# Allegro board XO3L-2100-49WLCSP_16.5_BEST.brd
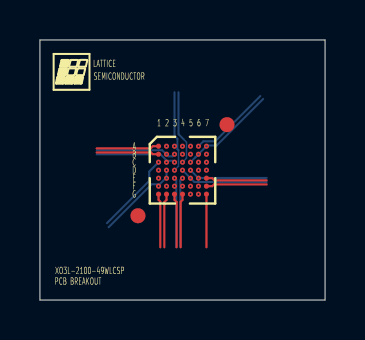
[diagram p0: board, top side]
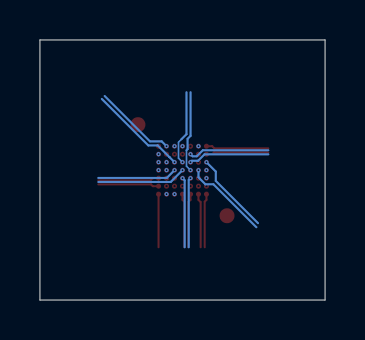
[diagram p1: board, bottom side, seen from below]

Outline 14.28 x 13.02 mm; copper layers: TOP, L2_SIG, L3_PWR_GND, BOTTOM. Coordinates in mm from the lower left corner of the outline.
Outline path: 0,13.02 0,0 14.28,0 14.28,13.02 0,13.02

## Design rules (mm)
net group CDPT20: nets PT20C PT20D
net group CDPT24: nets PT24C PT24D
net group LVDSI_14_PB12: nets LVDSI_14_PB12A LVDSI_14_PB12B
net group LVDSI_23_PB3: nets LVDSI_23_PB3A LVDSI_23_PB3B
net group LVDSI_PB11: nets LVDSI_PB11A LVDSI_PB11B
net group LVDSI_PB16: nets LVDSI_PB16A LVDSI_PB16B
net group LVDSI_PB25: nets LVDSI_PB25A LVDSI_PB25B
net group LVDSO_4_PT17: nets LVDSO_4_PT17A LVDSO_4_PT17B
net group PB8: nets PB8A PB8B
net group PL2: nets PL2A PL2B
net group PL3: nets PL3A PL3B
net group PL5: nets PL5A PL5B
net group PT10: nets PT10A PT10B
net group PT12: nets PT12C PT12D
net group PT16: nets PT16C PT16D
net group PT18: nets PT18C PT18D
net group PT20: nets PT20A PT20B
net group PT23: nets PT23A PT23B
net group PT24: nets PT24A PT24B

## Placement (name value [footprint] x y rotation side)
BGA  -  [BGA49N40P7X7_317X310X60B26N]  7.14 6.5 270 top
NOREF  -  []  0.41 10.21 0 top

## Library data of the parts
BGA = BGA49N40P7X7_317X310X60B26N

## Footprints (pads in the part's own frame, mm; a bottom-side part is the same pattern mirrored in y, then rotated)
BGA49N40P7X7_317X310X60B26N
  round 0.75 smd: (-2.28,2.23) (2.28,-2.23)
  round 0.254 smd: A1(-1.2,-1.2) A2(-1.2,-0.8) A3(-1.2,-0.4) A4(-1.2,0) A5(-1.2,0.4) A6(-1.2,0.8) A7(-1.2,1.2) B1(-0.8,-1.2) B2(-0.8,-0.8) B3(-0.8,-0.4) B4(-0.8,0) B5(-0.8,0.4) B6(-0.8,0.8) B7(-0.8,1.2) C1(-0.4,-1.2) C2(-0.4,-0.8) C3(-0.4,-0.4) C4(-0.4,0) C5(-0.4,0.4) C6(-0.4,0.8) C7(-0.4,1.2) D1(0,-1.2) D2(0,-0.8) D3(0,-0.4) D4(0,0) D5(0,0.4) D6(0,0.8) D7(0,1.2) E1(0.4,-1.2) E2(0.4,-0.8) E3(0.4,-0.4) E4(0.4,0) E5(0.4,0.4) E6(0.4,0.8) E7(0.4,1.2) F1(0.8,-1.2) F2(0.8,-0.8) F3(0.8,-0.4) F4(0.8,0) F5(0.8,0.4) F6(0.8,0.8) F7(0.8,1.2) G1(1.2,-1.2) G2(1.2,-0.8) G3(1.2,-0.4) G4(1.2,0) G5(1.2,0.4) G6(1.2,0.8) G7(1.2,1.2)

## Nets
GND: BGA.A4 BGA.D6 BGA.E1 BGA.G5
VCC: BGA.D1 BGA.D7
VCCIO0: BGA.A2 BGA.A5
VCCIO2: BGA.G6
VCCIO5: BGA.B7
LVDSI_14_PB12A: BGA.F4
LVDSI_14_PB12B: BGA.F3
LVDSI_23_PB3A: BGA.E7
LVDSI_23_PB3B: BGA.F7
LVDSI_PB11A: BGA.E4
LVDSI_PB11B: BGA.E3
LVDSI_PB16A: BGA.G4
LVDSI_PB16B: BGA.G3
LVDSI_PB25A: BGA.G2
LVDSI_PB25B: BGA.G1
LVDSO_4_PT17A: BGA.C4
LVDSO_4_PT17B: BGA.D3
PB5A: BGA.G7
PB8A: BGA.F6
PB8B: BGA.F5
PL2A: BGA.A7
PL2B: BGA.B6
PL3A: BGA.C7
PL3B: BGA.C6
PL5A: BGA.E6
PL5B: BGA.E5
PT10A: BGA.D5
PT10B: BGA.D4
PT12C: BGA.A6
PT12D: BGA.C5
PT16C: BGA.B4
PT16D: BGA.B5
PT18C: BGA.B3
PT18D: BGA.C3
PT20A: BGA.A3
PT20B: BGA.B2
PT20C: BGA.F2
PT20D: BGA.F1
PT23A: BGA.E2
PT23B: BGA.C2
PT24A: BGA.C1
PT24B: BGA.D2
PT24C: BGA.B1
PT24D: BGA.A1

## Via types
v1: diameter 0.203, hole 0.102, TOP to L2_SIG, 16 vias
v2: diameter 0.203, hole 0.102, TOP to BOTTOM, 24 vias

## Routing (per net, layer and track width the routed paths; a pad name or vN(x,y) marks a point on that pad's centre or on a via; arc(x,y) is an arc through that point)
GND:
  vias: v2(5.94,6.1) v2(7.14,7.7) v2(7.54,5.3) v2(7.94,6.5)
VCC:
  vias: v2(5.94,6.5) v2(8.34,6.5)
VCCIO0:
  vias: v2(6.34,7.7) v2(7.54,7.7)
VCCIO2:
  vias: v2(7.94,5.3)
VCCIO5:
  vias: v2(8.34,7.3)
LVDSI_14_PB12A: length 3.1
  L2_SIG w0.102: 7.04,2.64 7.04,5.6 v1(7.14,5.7)
LVDSI_14_PB12B: length 3.1
  L2_SIG w0.102: 6.84,2.64 6.84,5.6 v1(6.74,5.7)
LVDSI_23_PB3A: length 3.1
  TOP w0.102: 11.35,5.99 8.74,5.99 8.63,6.1 BGA.E7
LVDSI_23_PB3B: length 3.1
  TOP w0.102: BGA.F7 8.63,5.7 8.72,5.79 11.35,5.79
LVDSI_PB11A: length 3.5
  BOTTOM w0.102: v2(7.14,6.1) 7.03,5.99 7.03,2.64
LVDSI_PB11B: length 3.5
  BOTTOM w0.102: v2(6.74,6.1) 6.83,6.01 6.83,2.64
LVDSI_PB16A: length 2.7
  TOP w0.102: 7.05,2.64 7.05,4.92 7.14,5.01 BGA.G4
LVDSI_PB16B: length 2.7
  TOP w0.102: BGA.G3 6.74,5.01 6.85,4.9 6.85,2.64
LVDSI_PB25A: length 2.7
  TOP w0.102: BGA.G2 6.34,5.01 6.23,4.9 6.23,2.64
LVDSI_PB25B: length 2.7
  TOP w0.102: BGA.G1 5.94,5.01 6.03,4.93 6.03,2.64
LVDSO_4_PT17A: length 3.7
  BOTTOM w0.076: v2(7.14,6.9) 7.34,7.1 7.34,7.9 7.19,8.05
  BOTTOM w0.102: 6.94,10.4 6.94,8.3 7.19,8.05
LVDSO_4_PT17B: length 4.1
  BOTTOM w0.076: 6.94,7.5 6.94,6.7 v2(6.74,6.5)
  BOTTOM w0.102: 6.74,10.4 6.74,8.22 6.88,8.07 6.88,7.56 6.94,7.5
PB5A: length 2.7
  TOP w0.102: BGA.G7 8.34,2.64
PB8A: length 3.2
  L2_SIG w0.076: 8.14,5.14 8.14,5.5 v1(7.94,5.7)
  L2_SIG w0.102: 8.03,2.64 8.03,4.91 8.14,5.02 8.14,5.14
PB8B: length 3.2
  L2_SIG w0.076: v1(7.54,5.7) 7.74,5.5 7.74,5.15
  L2_SIG w0.102: 7.74,5.15 7.74,5.03 7.83,4.94 7.83,2.64
PL2A: length 3.8
  L2_SIG w0.102: 11.09,10.16 8.63,7.7 v1(8.34,7.7)
PL2B: length 4.4
  L2_SIG w0.076: 8.53,7.5 8.14,7.5 v1(7.94,7.3)
  L2_SIG w0.102: 8.53,7.5 8.72,7.5 11.23,10.01
PL3A: length 3.1
  L2_SIG w0.102: 11.35,7.19 8.63,7.19 v2(8.34,6.9)
PL3B: length 3.6
  L2_SIG w0.076: v2(7.94,6.9) 8.14,6.7 8.55,6.7 8.66,6.82
  L2_SIG w0.102: 11.35,6.99 8.83,6.99 8.66,6.82
PL5A: length 3.5
  L2_SIG w0.102: v1(7.94,6.1) 8.19,6.1 8.37,5.93 11.35,5.93
PL5B: length 4
  L2_SIG w0.076: v1(7.54,6.1) 7.74,6.3 8.28,6.3 8.39,6.19
  L2_SIG w0.102: 8.39,6.19 8.45,6.13 11.35,6.13
PT10A: length 4
  BOTTOM w0.102: v2(7.54,6.5) 7.93,6.11 11.35,6.11
PT10B: length 4.5
  BOTTOM w0.102: v2(7.14,6.5) 7.73,5.91 11.35,5.91
PT12C: length 4.1
  BOTTOM w0.102: v2(7.94,7.7) 8.18,7.94 8.77,7.94 11.04,10.21
PT12D: length 5
  BOTTOM w0.102: v2(7.54,6.9) 7.79,7.15 8.38,7.74 8.85,7.74 11.18,10.07
PT16C: length 3.2
  L2_SIG w0.076: v1(7.14,7.3) 7.34,7.5 7.34,7.86
  L2_SIG w0.102: 7.43,10.4 7.43,8.1 7.34,8.01 7.34,7.86
PT16D: length 3.2
  L2_SIG w0.076: v1(7.54,7.3) 7.74,7.5 7.74,7.85
  L2_SIG w0.102: 7.64,10.4 7.64,8.13 7.74,8.03 7.74,7.85
PT18C: length 4.1
  BOTTOM w0.102: v2(6.74,7.3) 6.64,7.2 6.42,7.2 6.12,7.5 2.84,7.5
PT18D: length 4.1
  BOTTOM w0.102: v2(6.74,6.9) 6.67,6.97 6.36,6.97 6.04,7.3 2.84,7.3
PT20A: length 3.8
  L2_SIG w0.102: 3.96,10.27 6.12,8.11 6.33,8.11 v1(6.74,7.7)
PT20B: length 3.9
  L2_SIG w0.102: 3.82,10.13 5.97,7.98 5.97,7.67 v1(6.34,7.3)
PT20C: length 3.1
  L2_SIG w0.102: v1(6.34,5.7) 6.24,5.6 6.24,2.64
PT20D: length 3.1
  L2_SIG w0.102: v1(5.94,5.7) 6.04,5.6 6.04,2.64
PT23A: length 3.6
  L2_SIG w0.076: v1(6.34,6.1) 6.14,6.3 5.74,6.3
  L2_SIG w0.102: 2.84,6.44 5.44,6.44 5.58,6.3 5.74,6.3
PT23B: length 3.6
  L2_SIG w0.076: v1(6.34,6.9) 6.14,6.7 5.74,6.7
  L2_SIG w0.102: 2.84,6.65 5.51,6.65 5.56,6.7 5.74,6.7
PT24A: length 4.1
  BOTTOM w0.102: 3.36,3.85 5.47,5.96 5.47,6.43 v2(5.94,6.9)
PT24B: length 4.3
  BOTTOM w0.102: 3.44,3.65 5.59,5.8 5.99,5.8 6.34,6.14 v2(6.34,6.5)
PT24C: length 3.1
  TOP w0.102: BGA.B1 5.65,7.3 5.56,7.39 2.84,7.39
PT24D: length 3.1
  TOP w0.102: BGA.A1 5.65,7.7 5.54,7.59 2.84,7.59

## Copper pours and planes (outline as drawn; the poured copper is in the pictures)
GND on L3_PWR_GND: 7.18,7.81 7.52,7.47 8.05,7.47 8.05,6.35 7.75,6.35 7.27,6.83 5.67,6.83 5.67,6.27 6,6.27 6.1,6.17 6.1,5.74 7.67,5.74 7.67,4.77 5.46,4.77 5.46,7.39 6.41,7.39 6.83,7.81
VCC on L3_PWR_GND: 5.77,6.73 7.22,6.73 7.65,6.3 8.13,6.3 8.13,6.78 8.87,6.78 8.87,5.84 6.17,5.84 6.17,6.22 6.05,6.35 5.77,6.35
VCCIO0 on L3_PWR_GND: 5.46,7.49 6.35,7.49 6.76,7.89 7.24,7.89 7.57,7.57 8.87,7.57 8.87,8.25 5.46,8.25
VCCIO2 on L3_PWR_GND: 7.77,5.71 7.77,4.77 8.89,4.77 8.89,5.71

Small or netless copper shapes (teardrops, artwork), in the pictures only: 1 on L3_PWR_GND

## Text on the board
User.Comments: ASP | 06/30/14. | DWG NO: | XO3L-2100-49WLCSP | REVISION | 2.0 | SHEET | 1 | OF | XO3L-2100-49WLCSP PCB BREAKOUT | LATTICE SEMICONDUCTOR CORPORATION
Ref Des/Silkscreen Top: PCB BREAKOUT | XO3L-2100-49WLCSP | LATTICE | SEMICONDUCTOR | A | B | C | D | E | F | G | 1 | 2 | 3 | 4 | 5 | 6 | 7
PAGE_OUTLINE: SPECIAL INSTRUCTIONS: | USE 1/2 OUNCE COPPER FOR BOTH INTERNAL AND EXTERNAL LAYERS | VIAS ARE TO BE NON-CONDUCTIVE EPOXY FILLED | PLANARIZE AT TOP AND BOTTOM | BOARD THICKNESS IS 62MILS | SIGNAL         (L2) | POWER/GND PLANE (L3) | PRIMARY SIDE   (L1) | SECONDARY SIDE (L4) | SECONDARY SILKSCREEN | SECONDARY SOLDERMASK | PRIMARY SOLDERMASK | PRIMARY SILKSCREEN | DESIGNED BY: | APPROVED BY: | SIGNATURES         DATE | REV | 1 | INITIAL RELEASE | ESCAPE VIA DRILL | TRACE WIDTH/SPACE | ARRAY SIZE | ESCAPE VIA PAD | BGA LAND OPENING | PACKAGE SIZE | BGA LAND PAD | PITCH | DESCRIPTION | 3.185x3.106 | 0.0762 | 0.1016 | 0.2032 | 0.3048 | 7 X 7 | 0.40 | MM | MM/DD/YYYY | DATE | 12.00 | 15.748 | MILS | 8.00 | 4.00 | 4/3 | APPROVED | XXXXXXXXX | 4 LAYER STACKUP | PCB BREAKOUT DETAILS | REVISION
PLACE_BOUND_TOP: FIGURE | SIZE | 4.0 | ALL UNITS ARE IN MILS | SIZE MM | 0.1016 | PLATED | QTY | 10 | DRILL CHART: TOP to L4_SIG
DISPLAY_TOP: FIGURE | SIZE | 4.0 | ALL UNITS ARE IN MILS | SIZE MM | 0.1016 | PLATED | QTY | 16 | DRILL CHART: TOP to BOTTOM
DEVICE_TYPE_TOP: FIGURE | SIZE | 4.0 | ALL UNITS ARE IN MILS | SIZE MM | 0.1016 | PLATED | QTY | 14 | DRILL CHART: TOP to L3_SIG
